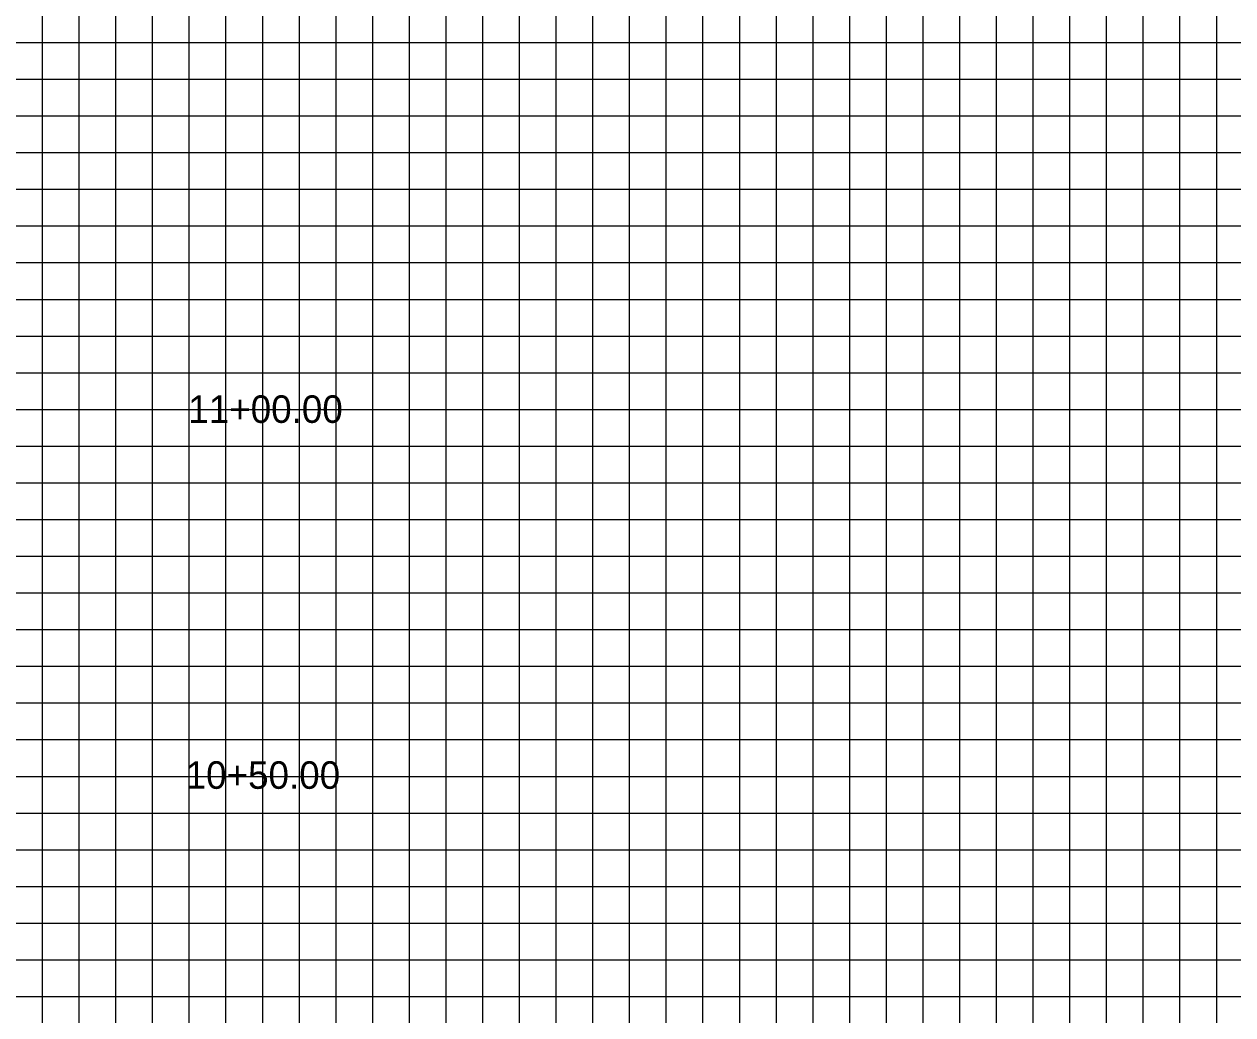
# Model space of a CAD drawing. Extents: x 967 to 1326, y 964 to 2864.
# Drawn here: x 1147 to 1212.9, y 1019 to 1073 of the extents above; entities that cross this region are included whole.
import ezdxf

# ---------------------------------------------------------------- set-up
doc = ezdxf.new("R2010")
doc.units = 0
for name, color, linetype in [('Default', 7, 'Continuous'), ('RD_EX_RW', 7, 'Continuous'), ('RD_SHT_ShtClip', 7, 'Continuous')]:
    doc.layers.add(name, color=color, linetype=linetype)

msp = doc.modelspace()

# ---------------------------------------------------------------- linework, layer by layer
at = {"layer": 'RD_EX_RW'}
for p, q in [((1150, 1000), (1150, 1170)), ((1160, 1000), (1160, 1170)), ((1170, 1000), (1170, 1170)), ((1180, 1000), (1180, 1170)), ((1190, 1000), (1190, 1170)), ((1200, 1000), (1200, 1170)), ((1210, 1000), (1210, 1170)), ((1000, 1070), (1320, 1070)), ((1000, 1060), (1320, 1060)), ((1000, 1050), (1320, 1050)), ((1000, 1040), (1320, 1040)), ((1000, 1030), (1320, 1030)), ((1000, 1020), (1320, 1020))]:
    msp.add_line(p, q, dxfattribs=at)
at = {"layer": 'RD_SHT_ShtClip'}
for p, q in [((1148, 1000), (1148, 1170)), ((1152, 1000), (1152, 1170)), ((1154, 1000), (1154, 1170)), ((1156, 1000), (1156, 1170)), ((1158, 1000), (1158, 1170)), ((1162, 1000), (1162, 1170)), ((1164, 1000), (1164, 1170)), ((1166, 1000), (1166, 1170)), ((1168, 1000), (1168, 1170)), ((1172, 1000), (1172, 1170)), ((1174, 1000), (1174, 1170)), ((1176, 1000), (1176, 1170)), ((1178, 1000), (1178, 1170)), ((1182, 1000), (1182, 1170)), ((1184, 1000), (1184, 1170)), ((1186, 1000), (1186, 1170)), ((1188, 1000), (1188, 1170)), ((1192, 1000), (1192, 1170)), ((1194, 1000), (1194, 1170)), ((1196, 1000), (1196, 1170)), ((1198, 1000), (1198, 1170)), ((1202, 1000), (1202, 1170)), ((1204, 1000), (1204, 1170)), ((1206, 1000), (1206, 1170)), ((1208, 1000), (1208, 1170)), ((1212, 1000), (1212, 1170)), ((1000, 1072), (1320, 1072)), ((1000, 1068), (1320, 1068)), ((1000, 1066), (1320, 1066)), ((1000, 1064), (1320, 1064)), ((1000, 1062), (1320, 1062)), ((1000, 1058), (1320, 1058)), ((1000, 1056), (1320, 1056)), ((1000, 1054), (1320, 1054)), ((1000, 1052), (1320, 1052)), ((1000, 1048), (1320, 1048)), ((1000, 1046), (1320, 1046)), ((1000, 1044), (1320, 1044)), ((1000, 1042), (1320, 1042)), ((1000, 1038), (1320, 1038)), ((1000, 1036), (1320, 1036)), ((1000, 1034), (1320, 1034)), ((1000, 1032), (1320, 1032)), ((1000, 1028), (1320, 1028)), ((1000, 1026), (1320, 1026)), ((1000, 1024), (1320, 1024)), ((1000, 1022), (1320, 1022))]:
    msp.add_line(p, q, dxfattribs=at)

# ---------------------------------------------------------------- texts
at = {"layer": 'Default'}
for s, p in [('11+00.00', (1155.945, 1051.266)), ('10+50.00', (1155.801, 1031.32))]:
    msp.add_text(s, height=1.5, dxfattribs=at).set_placement(p)

doc.saveas('drawing.dxf')
